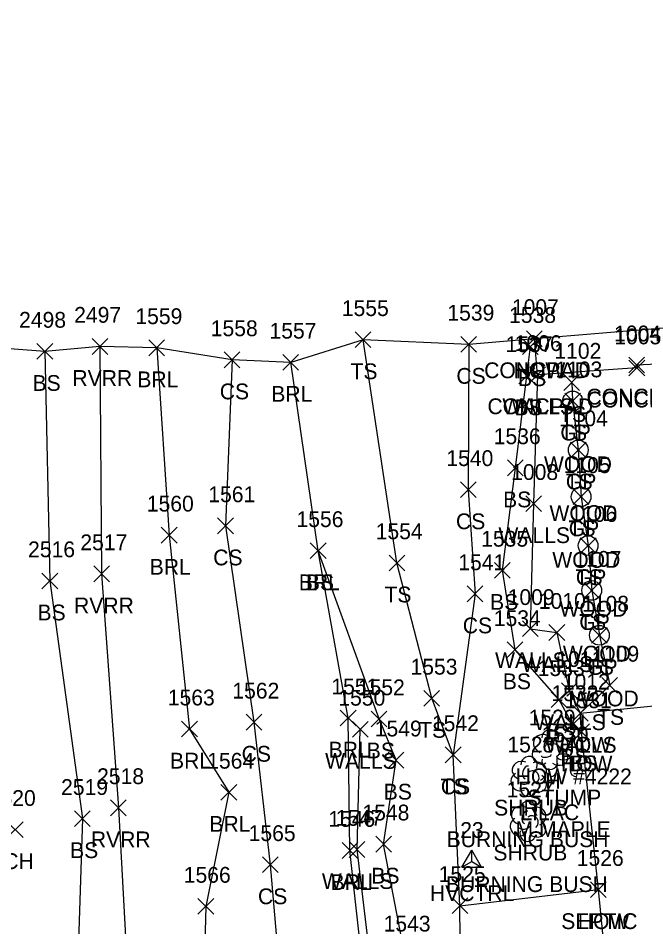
# Model space of a CAD drawing. Extents: x 1512665 to 1513714, y 110636 to 112816.
# Drawn here: x 1513047.2 to 1513126.6, y 111019.1 to 111134.2 of the extents above; entities that cross this region are included whole.
import ezdxf

# ---------------------------------------------------------------- set-up
doc = ezdxf.new("R2010")
doc.units = 0
for name, color, linetype in [('C_A', 7, 'Continuous'), ('C_I', 7, 'Continuous'), ('CPSM', 7, 'Continuous'), ('L_A', 7, 'Continuous'), ('L_C', 7, 'Continuous'), ('L_I', 7, 'Continuous'), ('L_TIC', 7, 'Continuous'), ('LABL', 7, 'Continuous'), ('LAWE', 7, 'Continuous'), ('LBC', 7, 'Continuous'), ('LELB', 7, 'Continuous'), ('Level 13', 7, 'Continuous'), ('LS', 7, 'Continuous'), ('LSH', 7, 'Continuous'), ('LSOGP', 7, 'Continuous'), ('LTD', 7, 'Continuous'), ('LTS', 7, 'Continuous'), ('LWS', 7, 'Continuous'), ('R_A', 7, 'Continuous'), ('R_C', 7, 'Continuous'), ('R_I', 7, 'Continuous'), ('RGP', 7, 'Continuous'), ('U_A', 7, 'Continuous'), ('U_I', 7, 'Continuous'), ('U_TIC', 7, 'Continuous'), ('USA', 7, 'Continuous')]:
    doc.layers.add(name, color=color, linetype=linetype)

msp = doc.modelspace()

# ---------------------------------------------------------------- linework, layer by layer
at = {"layer": 'CPSM'}
for p, q in [((1513103.4, 111026.62), (1513104.65, 111028.78)), ((1513105.9, 111026.62), (1513104.65, 111028.78)), ((1513104.65, 111027.34), (1513104.65, 111028.78)), ((1513103.4, 111026.62), (1513104.65, 111027.34)), ((1513104.65, 111027.34), (1513104.65, 111027.34)), ((1513104.65, 111027.34), (1513105.9, 111026.62)), ((1513103.4, 111026.62), (1513105.9, 111026.62))]:
    msp.add_line(p, q, dxfattribs=at)
at = {"layer": 'L_TIC'}
for points in [[(1513056.55, 111091.59), (1513058.55, 111093.59)], [(1513058.55, 111091.59), (1513056.55, 111093.59)], [(1513089.88, 111092.44), (1513091.88, 111094.44)], [(1513091.88, 111092.44), (1513089.88, 111094.44)], [(1513103.26, 111091.86), (1513105.26, 111093.86)], [(1513105.26, 111091.86), (1513103.26, 111093.86)], [(1513111.07, 111091.57), (1513113.07, 111093.57)], [(1513113.07, 111091.57), (1513111.07, 111093.57)], [(1513111.58, 111092.57), (1513113.58, 111094.57)], [(1513113.58, 111092.57), (1513111.58, 111094.57)], [(1513111.58, 111092.57), (1513113.58, 111094.57)], [(1513113.58, 111092.57), (1513111.58, 111094.57)], [(1513049.57, 111090.96), (1513051.57, 111092.96)], [(1513051.57, 111090.96), (1513049.57, 111092.96)], [(1513063.74, 111091.42), (1513065.74, 111093.42)], [(1513065.74, 111091.42), (1513063.74, 111093.42)], [(1513073.29, 111089.89), (1513075.29, 111091.89)], [(1513075.29, 111089.89), (1513073.29, 111091.89)], [(1513080.72, 111089.58), (1513082.72, 111091.58)], [(1513082.72, 111089.58), (1513080.72, 111091.58)], [(1513124.53, 111089.23), (1513126.53, 111091.23)], [(1513126.53, 111089.23), (1513124.53, 111091.23)], [(1513124.56, 111088.86), (1513126.56, 111090.86)], [(1513126.56, 111088.86), (1513124.56, 111090.86)], [(1513110.62, 111087.87), (1513112.62, 111089.87)], [(1513112.62, 111087.87), (1513110.62, 111089.87)], [(1513111.99, 111088.01), (1513113.99, 111090.01)], [(1513113.99, 111088.01), (1513111.99, 111090.01)], [(1513111.99, 111088.01), (1513113.99, 111090.01)], [(1513113.99, 111088.01), (1513111.99, 111090.01)], [(1513116.31, 111087.03), (1513118.31, 111089.03)], [(1513118.31, 111087.03), (1513116.31, 111089.03)], [(1513116.43, 111084.68), (1513118.43, 111086.68)], [(1513118.43, 111084.68), (1513116.43, 111086.68)], [(1513117.14, 111078.48), (1513119.14, 111080.48)], [(1513119.14, 111078.48), (1513117.14, 111080.48)], [(1513109.18, 111076.21), (1513111.18, 111078.21)], [(1513111.18, 111076.21), (1513109.18, 111078.21)], [(1513103.21, 111073.44), (1513105.21, 111075.44)], [(1513105.21, 111073.44), (1513103.21, 111075.44)], [(1513117.5, 111072.55), (1513119.5, 111074.55)], [(1513119.5, 111072.55), (1513117.5, 111074.55)], [(1513111.49, 111071.68), (1513113.49, 111073.68)], [(1513113.49, 111071.68), (1513111.49, 111073.68)], [(1513072.46, 111068.86), (1513074.46, 111070.86)], [(1513074.46, 111068.86), (1513072.46, 111070.86)], [(1513065.32, 111067.68), (1513067.32, 111069.68)], [(1513067.32, 111067.68), (1513065.32, 111069.68)], [(1513118.39, 111066.36), (1513120.39, 111068.36)], [(1513120.39, 111066.36), (1513118.39, 111068.36)], [(1513084.19, 111065.71), (1513086.19, 111067.71)], [(1513086.19, 111065.71), (1513084.19, 111067.71)], [(1513084.19, 111065.71), (1513086.19, 111067.71)], [(1513086.19, 111065.71), (1513084.19, 111067.71)], [(1513094.18, 111064.17), (1513096.18, 111066.17)], [(1513096.18, 111064.17), (1513094.18, 111066.17)], [(1513107.53, 111063.23), (1513109.53, 111065.23)], [(1513109.53, 111063.23), (1513107.53, 111065.23)], [(1513050.2, 111061.89), (1513052.2, 111063.89)], [(1513052.2, 111061.89), (1513050.2, 111063.89)], [(1513056.76, 111062.78), (1513058.76, 111064.78)], [(1513058.76, 111062.78), (1513056.76, 111064.78)], [(1513118.84, 111060.68), (1513120.84, 111062.68)], [(1513120.84, 111060.68), (1513118.84, 111062.68)], [(1513104.07, 111060.25), (1513106.07, 111062.25)], [(1513106.07, 111060.25), (1513104.07, 111062.25)], [(1513111.06, 111055.84), (1513113.06, 111057.84)], [(1513113.06, 111055.84), (1513111.06, 111057.84)], [(1513114.43, 111055.35), (1513116.43, 111057.35)], [(1513116.43, 111055.35), (1513114.43, 111057.35)], [(1513119.82, 111055), (1513121.82, 111057)], [(1513121.82, 111055), (1513119.82, 111057)], [(1513109.14, 111053.17), (1513111.14, 111055.17)], [(1513111.14, 111053.17), (1513109.14, 111055.17)], [(1513116, 111047.99), (1513118, 111049.99)], [(1513118, 111047.99), (1513116, 111049.99)], [(1513121.12, 111048.66), (1513123.12, 111050.66)], [(1513123.12, 111048.66), (1513121.12, 111050.66)], [(1513098.58, 111047.02), (1513100.58, 111049.02)], [(1513100.58, 111047.02), (1513098.58, 111049.02)], [(1513114.71, 111046.84), (1513116.71, 111048.84)], [(1513116.71, 111046.84), (1513114.71, 111048.84)], [(1513087.99, 111044.52), (1513089.99, 111046.52)], [(1513089.99, 111044.52), (1513087.99, 111046.52)], [(1513091.91, 111044.41), (1513093.91, 111046.41)], [(1513093.91, 111044.41), (1513091.91, 111046.41)], [(1513117.39, 111045.13), (1513119.39, 111047.13)], [(1513119.39, 111045.13), (1513117.39, 111047.13)], [(1513117.39, 111045.13), (1513119.39, 111047.13)], [(1513119.39, 111045.13), (1513117.39, 111047.13)], [(1513117.39, 111045.13), (1513119.39, 111047.13)], [(1513119.39, 111045.13), (1513117.39, 111047.13)], [(1513076.06, 111043.99), (1513078.06, 111045.99)], [(1513078.06, 111043.99), (1513076.06, 111045.99)], [(1513116.44, 111043.66), (1513118.44, 111045.66)], [(1513118.44, 111043.66), (1513116.44, 111045.66)], [(1513067.89, 111043.12), (1513069.89, 111045.12)], [(1513069.89, 111043.12), (1513067.89, 111045.12)], [(1513089.53, 111043.09), (1513091.53, 111045.09)], [(1513091.53, 111043.09), (1513089.53, 111045.09)], [(1513117.56, 111042.77), (1513119.56, 111044.77)], [(1513119.56, 111042.77), (1513117.56, 111044.77)], [(1513117.56, 111042.77), (1513119.56, 111044.77)], [(1513119.56, 111042.77), (1513117.56, 111044.77)], [(1513117.56, 111042.77), (1513119.56, 111044.77)], [(1513119.56, 111042.77), (1513117.56, 111044.77)], [(1513101.29, 111039.86), (1513103.29, 111041.86)], [(1513103.29, 111039.86), (1513101.29, 111041.86)], [(1513101.29, 111039.86), (1513103.29, 111041.86)], [(1513103.29, 111039.86), (1513101.29, 111041.86)], [(1513094.06, 111039.19), (1513096.06, 111041.19)], [(1513096.06, 111039.19), (1513094.06, 111041.19)], [(1513072.88, 111035.11), (1513074.88, 111037.11)], [(1513074.88, 111035.11), (1513072.88, 111037.11)], [(1513058.89, 111033.15), (1513060.89, 111035.15)], [(1513060.89, 111033.15), (1513058.89, 111035.15)], [(1513054.33, 111031.78), (1513056.33, 111033.78)], [(1513056.33, 111031.78), (1513054.33, 111033.78)], [(1513045.82, 111030.39), (1513047.82, 111032.39)], [(1513047.82, 111030.39), (1513045.82, 111032.39)], [(1513092.49, 111028.55), (1513094.49, 111030.55)], [(1513094.49, 111028.55), (1513092.49, 111030.55)], [(1513088.22, 111027.74), (1513090.22, 111029.74)], [(1513090.22, 111027.74), (1513088.22, 111029.74)], [(1513089.12, 111027.87), (1513091.12, 111029.87)], [(1513091.12, 111027.87), (1513089.12, 111029.87)], [(1513078.13, 111025.94), (1513080.13, 111027.94)], [(1513080.13, 111025.94), (1513078.13, 111027.94)], [(1513119.69, 111022.79), (1513121.69, 111024.79)], [(1513121.69, 111022.79), (1513119.69, 111024.79)], [(1513069.96, 111020.66), (1513071.96, 111022.66)], [(1513071.96, 111020.66), (1513069.96, 111022.66)], [(1513102.15, 111020.75), (1513104.15, 111022.75)], [(1513104.15, 111020.75), (1513102.15, 111022.75)]]:
    msp.add_lwpolyline(points, dxfattribs=at)
at = {"layer": 'LABL'}
for points in [[(1513064.74, 111092.42), (1513066.32, 111068.68), (1513068.89, 111044.12), (1513073.88, 111036.11), (1513070.96, 111021.66), (1513070.42, 111001.37), (1513070.1, 110988.57), (1513073.06, 110969.79), (1513079.94, 110970.83), (1513085.92, 110971.63)], [(1513094.41, 110975.3), (1513092.4, 110994.9), (1513090.91, 111013.45), (1513089.22, 111028.74), (1513088.99, 111045.52), (1513085.19, 111066.71), (1513081.72, 111090.58)]]:
    msp.add_lwpolyline(points, dxfattribs=at)
at = {"layer": 'LAWE'}
msp.add_lwpolyline([(1513057.55, 111092.59), (1513057.76, 111063.78), (1513059.89, 111034.15), (1513061.78, 110999.93), (1513066.11, 110974.8), (1513067.08, 110953.86)], dxfattribs=at)
at = {"layer": 'LBC'}
for points in [[(1513134.02, 111127.97), (1513137.06, 111095.56), (1513112.58, 111093.57)], [(1513118.39, 111046.13), (1513128.97, 111047.21), (1513141.84, 111048.52), (1513143.29, 111036.99), (1513150.61, 111037.66), (1513151.29, 111036.53), (1513151.86, 111031.98), (1513152.24, 111029.89), (1513144.2, 111028.94), (1513145.36, 111017.71), (1513137.39, 111016.83), (1513138.65, 111001.1), (1513139.17, 110995.77), (1513139.38, 110992.13), (1513138.77, 110991.85), (1513123.65, 110990.59), (1513123.34, 110990.75), (1513123.27, 110992.81), (1513122.61, 111004.46), (1513120.69, 111023.79), (1513118.56, 111043.77)], [(1513118.39, 111046.13), (1513118.56, 111043.77)]]:
    msp.add_lwpolyline(points, dxfattribs=at)
at = {"layer": 'LELB'}
for points in [[(1513103.15, 111021.75), (1513102.29, 111040.86), (1513099.58, 111048.02), (1513095.18, 111065.17), (1513090.88, 111093.44)], [(1513104.26, 111092.86), (1513104.21, 111074.44), (1513105.07, 111061.25), (1513102.29, 111040.86)], [(1513118.56, 111043.77), (1513117.44, 111044.66), (1513115.71, 111047.84), (1513110.14, 111054.17), (1513108.53, 111064.23), (1513110.18, 111077.21), (1513111.62, 111088.87), (1513112.07, 111092.57)], [(1513050.57, 111091.96), (1513051.2, 111062.89), (1513055.33, 111032.78), (1513054.28, 111000.38), (1513059.51, 110973.72), (1513056.82, 110953.44), (1513063.6, 110941.61), (1513067.13, 110927.73), (1513070.91, 110916.69), (1513076.1, 110900.54), (1513074.96, 110895.68), (1513079.69, 110884.14), (1513081.25, 110868.38), (1513078.34, 110857.81), (1513080.52, 110848.08), (1513078.46, 110838.38), (1513078.11, 110823.81), (1513078.51, 110819.27), (1513078.06, 110816.05), (1513076.99, 110814.7), (1513073.49, 110811.48), (1513073.8, 110795.94), (1513074.51, 110793.14), (1513077.43, 110790.98)], [(1513074.29, 111090.89), (1513073.46, 111069.86), (1513077.06, 111044.99), (1513079.13, 111026.94), (1513081.17, 111003.04), (1513084.44, 110991.21), (1513085.92, 110971.63), (1513087.54, 110964.28), (1513094.93, 110950.26), (1513100.49, 110942.42), (1513104.75, 110930.66), (1513102.64, 110919.33), (1513100.96, 110909.74), (1513100.96, 110887.48)], [(1513117.31, 111088.03), (1513117.43, 111085.68), (1513118.14, 111079.48), (1513118.5, 111073.55), (1513119.39, 111067.36), (1513119.84, 111061.68), (1513120.82, 111056), (1513122.12, 111049.66)], [(1513105.19, 110981.77), (1513102.58, 110989.9), (1513098.9, 111009.19), (1513096.17, 111015.48), (1513093.49, 111029.55), (1513095.06, 111040.19), (1513092.91, 111045.41), (1513085.19, 111066.71)], [(1513122.12, 111049.66), (1513118.39, 111046.13)]]:
    msp.add_lwpolyline(points, dxfattribs=at)
at = {"layer": 'Level 13'}
msp.add_lwpolyline([(1513123.64, 110990.61), (1513123.35, 110990.76), (1513123.29, 110992.81), (1513122.62, 111004.46), (1513120.7, 111023.79), (1513118.57, 111043.77), (1513118.4, 111046.12), (1513128.98, 111047.2), (1513141.84, 111048.51), (1513143.27, 111036.98), (1513150.61, 111037.65), (1513151.28, 111036.53), (1513151.85, 111031.98), (1513152.22, 111029.9), (1513144.19, 111028.96), (1513145.35, 111017.72), (1513137.37, 111016.84), (1513138.63, 111001.1), (1513139.16, 110995.77), (1513139.37, 110992.14), (1513138.78, 110991.85)], close=True, dxfattribs=at)
at = {"layer": 'LS'}
msp.add_lwpolyline([(1513137.06, 111095.56), (1513137.54, 111090.82), (1513125.53, 111090.23), (1513125.56, 111089.86), (1513112.99, 111089.01), (1513112.58, 111093.57)], dxfattribs=at)
at = {"layer": 'LSH'}
for p, q in [((1513111.85, 111038.17), (1513111.85, 111038.17)), ((1513111.85, 111038.17), (1513111.85, 111038.17)), ((1513111.76, 111032.48), (1513111.76, 111032.48)), ((1513111.76, 111032.48), (1513111.76, 111032.48))]:
    msp.add_line(p, q, dxfattribs=at)
for centre in [(1513111.9, 111039.6), (1513111.81, 111033.92)]:
    msp.add_arc(centre, 1.05, 335.5272, 180.9563, dxfattribs=at)
for centre, major_axis, ratio, start_param, end_param in [((1513111.06, 111038.84), (1.21, -0.51), 0.895232, 1.570796, 4.712389), ((1513111.64, 111038.63), (-0.208, -0.792), 0.645439, 3.141593, 6.283185), ((1513112.89, 111038.75), (-1.14, -0.48), 0.949671, 1.570796, 4.712389), ((1513110.77, 111037.46), (0.58, -1.04), 0.959034, 3.141593, 6.283185), ((1513112.35, 111038), (-0.5, 0.667), 0.989748, 3.141593, 6.283185), ((1513111.39, 111037.42), (-0.625, -0.083), 0.423636, 0, 3.141593), ((1513112.85, 111037.34), (-1.09, 0.79), 0.841452, 1.570796, 4.712389), ((1513111.85, 111036.67), (0.26, 1.06), 0.942809, 1.570796, 4.712389), ((1513110.97, 111033.15), (1.21, -0.51), 0.895232, 1.570796, 4.712389), ((1513111.55, 111032.94), (-0.208, -0.792), 0.645439, 3.141593, 6.283185), ((1513112.8, 111033.06), (-1.14, -0.48), 0.949671, 1.570796, 4.712389), ((1513110.68, 111031.77), (0.58, -1.04), 0.959034, 3.141593, 6.283185), ((1513112.26, 111032.31), (-0.5, 0.667), 0.989748, 3.141593, 6.283185), ((1513112.76, 111031.65), (-1.09, 0.79), 0.841452, 1.570796, 4.712389), ((1513111.3, 111031.73), (-0.625, -0.083), 0.423636, 0, 3.141593), ((1513111.76, 111030.98), (0.26, 1.06), 0.942809, 1.570796, 4.712389)]:
    msp.add_ellipse(centre, major_axis=major_axis, ratio=ratio, start_param=start_param, end_param=end_param, dxfattribs=at)
at = {"layer": 'LSOGP'}
msp.add_lwpolyline([(1513210.3, 111134.17), (1513195.74, 111132.86), (1513181.78, 111131.32), (1513177.7, 111131.29), (1513170.22, 111130.81), (1513157.92, 111130.1), (1513134.02, 111127.97), (1513137.06, 111095.56), (1513112.58, 111093.57), (1513104.26, 111092.85), (1513090.88, 111093.44), (1513081.72, 111090.57), (1513074.29, 111090.88), (1513064.74, 111092.42), (1513057.55, 111092.59), (1513050.57, 111091.96), (1513042.76, 111092.55)], dxfattribs=at)
at = {"layer": 'LTD'}
msp.add_line((1513114.55, 111041.58), (1513114.55, 111041.58), dxfattribs=at)
msp.add_line((1513114.55, 111041.58), (1513114.55, 111041.58), dxfattribs=at)
msp.add_arc((1513114.59, 111043.01), 1.05, 335.5272, 180.9563, dxfattribs=at)
for centre, major_axis, ratio, start_param, end_param in [((1513113.75, 111042.24), (1.21, -0.51), 0.895232, 1.570796, 4.712389), ((1513115.59, 111042.16), (-1.14, -0.48), 0.949671, 1.570796, 4.712389), ((1513113.46, 111040.87), (0.58, -1.04), 0.959034, 3.141593, 6.283185), ((1513114.34, 111042.04), (-0.208, -0.792), 0.645439, 3.141593, 6.283185), ((1513115.05, 111041.41), (-0.5, 0.667), 0.989748, 3.141593, 6.283185), ((1513114.09, 111040.83), (-0.625, -0.083), 0.423636, 0, 3.141593), ((1513115.55, 111040.74), (-1.09, 0.79), 0.841452, 1.570796, 4.712389), ((1513114.55, 111040.08), (0.26, 1.06), 0.942809, 1.570796, 4.712389)]:
    msp.add_ellipse(centre, major_axis=major_axis, ratio=ratio, start_param=start_param, end_param=end_param, dxfattribs=at)
at = {"layer": 'LTS'}
for p, q in [((1513115.43, 111040.59), (1513115.43, 111038.93)), ((1513117.1, 111040.43), (1513117.1, 111040.59)), ((1513117.1, 111040.59), (1513117.1, 111038.93)), ((1513116.27, 111039.45), (1513116.27, 111039.45)), ((1513116.27, 111039.45), (1513116.27, 111039.45)), ((1513116.27, 111039.43), (1513116.27, 111039.43))]:
    msp.add_line(p, q, dxfattribs=at)
msp.add_circle((1513116.27, 111039.45), 0.0833, dxfattribs=at)
for centre, start, end in [((1513114.6, 111038.93), 270, 360), ((1513117.93, 111038.93), 180, 270)]:
    msp.add_arc(centre, 0.833, start, end, dxfattribs=at)
msp.add_ellipse((1513116.27, 111040.59), major_axis=(-0.833, 0), ratio=0.5, dxfattribs=at)
at = {"layer": 'LWS'}
for points in [[(1513112.99, 111089.01), (1513112.49, 111072.68), (1513112.06, 111056.84), (1513115.43, 111056.35), (1513117, 111048.99), (1513118.39, 111046.13)], [(1513113.24, 110946.25), (1513110.87, 110954.65), (1513106.11, 110963.52), (1513095.31, 110975.46), (1513093.16, 110995.74), (1513091.91, 111014.04), (1513090.12, 111028.87), (1513090.53, 111044.09)]]:
    msp.add_lwpolyline(points, dxfattribs=at)
at = {"layer": 'RGP'}
for p, q in [((1513117.43, 111085.68), (1513117.43, 111085.68)), ((1513118.14, 111079.48), (1513118.14, 111079.48)), ((1513118.5, 111073.55), (1513118.5, 111073.55)), ((1513119.39, 111067.36), (1513119.39, 111067.36)), ((1513119.84, 111061.68), (1513119.84, 111061.68)), ((1513120.82, 111056), (1513120.82, 111056))]:
    msp.add_line(p, q, dxfattribs=at)
for centre, radius in [((1513117.43, 111085.68), 1.25), ((1513117.43, 111085.68), 0.0833), ((1513118.14, 111079.48), 1.25), ((1513118.14, 111079.48), 0.0833), ((1513118.5, 111073.55), 1.25), ((1513118.5, 111073.55), 0.0833), ((1513119.39, 111067.36), 1.25), ((1513119.39, 111067.36), 0.0833), ((1513119.84, 111061.68), 1.25), ((1513119.84, 111061.68), 0.0833), ((1513120.82, 111056), 1.25), ((1513120.82, 111056), 0.0833)]:
    msp.add_circle(centre, radius, dxfattribs=at)
at = {"layer": 'U_TIC'}
for points in [[(1513119.69, 111022.79), (1513121.69, 111024.79)], [(1513121.69, 111022.79), (1513119.69, 111024.79)], [(1513102.15, 111020.75), (1513104.15, 111022.75)], [(1513104.15, 111020.75), (1513102.15, 111022.75)]]:
    msp.add_lwpolyline(points, dxfattribs=at)
at = {"layer": 'USA'}
msp.add_lwpolyline([(1513119.97, 110992.38), (1513106.59, 110990.46), (1513103.28, 111009.25), (1513103.15, 111021.75), (1513120.69, 111023.79)], dxfattribs=at)

# ---------------------------------------------------------------- texts
at = {"layer": 'C_A'}
msp.add_text('HVCTRL', height=2, dxfattribs=at).set_placement((1513099.35, 111022.34))
at = {"layer": 'C_I'}
msp.add_text('23', height=2, dxfattribs=at).set_placement((1513103.19, 111030.34))
at = {"layer": 'L_A'}
for s, p in [('TS', (1513089.29, 111088.44)), ('CONCPAD', (1513106.22, 111088.57)), ('HOW', (1513109.96, 111088.57)), ('BS', (1513049.01, 111086.96)), ('RVRR', (1513054.06, 111087.59)), ('BRL', (1513062.29, 111087.42)), ('CS', (1513102.7, 111087.86)), ('BS', (1513110.51, 111087.57)), ('CS', (1513072.73, 111085.89)), ('BRL', (1513079.26, 111085.58)), ('CONCPAD', (1513119.18, 111085.23)), ('CONCPAD', (1513119.21, 111084.86)), ('CONCPAD', (1513106.64, 111084.01)), ('WALLS', (1513108.53, 111084.01)), ('BS', (1513110.06, 111083.87)), ('TS', (1513115.72, 111083.03)), ('TS', (1513115.84, 111080.68)), ('TS', (1513116.55, 111074.48)), ('BS', (1513108.62, 111072.21)), ('CS', (1513102.65, 111069.44)), ('TS', (1513116.91, 111068.55)), ('WALLS', (1513108.03, 111067.68)), ('CS', (1513071.9, 111064.86)), ('BRL', (1513063.86, 111063.68)), ('BRL', (1513082.74, 111061.71)), ('BS', (1513083.64, 111061.71)), ('TS', (1513117.8, 111062.36)), ('TS', (1513093.59, 111060.17)), ('RVRR', (1513054.27, 111058.78)), ('BS', (1513106.97, 111059.23)), ('BS', (1513049.64, 111057.89)), ('CS', (1513103.51, 111056.25)), ('TS', (1513118.25, 111056.68)), ('WALLS', (1513107.6, 111051.84)), ('WALLS', (1513110.97, 111051.35)), ('TS', (1513119.23, 111051)), ('BS', (1513108.58, 111049.17)), ('TS', (1513120.53, 111044.66)), ('WALLS', (1513112.55, 111043.99)), ('TS', (1513097.99, 111043.02)), ('BS', (1513114.15, 111042.84)), ('WALLS', (1513113.93, 111041.13)), ('HOW', (1513115.77, 111041.13)), ('HOW', (1513115.77, 111041.13)), ('CS', (1513075.5, 111039.99)), ('BRL', (1513086.53, 111040.52)), ('BS', (1513091.35, 111040.41)), ('BRL', (1513066.43, 111039.12)), ('WALLS', (1513086.07, 111039.09)), ('BS', (1513115.88, 111039.66)), ('HOW', (1513115.94, 111038.77)), ('HOW', (1513115.94, 111038.77)), ('BS', (1513117, 111038.77)), ('H', (1513113.98, 111036.58)), ('BS', (1513093.5, 111035.19)), ('TS', (1513100.7, 111035.86)), ('CS', (1513100.73, 111035.86)), ('STUMP', (1513111.69, 111034.45)), ('SHRUB', (1513107.48, 111033.17)), ('BRL', (1513071.42, 111031.11)), ('RVRR', (1513056.4, 111029.15)), ('BS', (1513053.77, 111027.78)), ('SHRUB', (1513107.39, 111027.48)), ('CH', (1513045.31, 111026.39)), ('WALLS', (1513085.66, 111023.87)), ('BRL', (1513086.77, 111023.74)), ('BS', (1513091.93, 111024.55)), ('CS', (1513077.57, 111021.94)), ('HOW', (1513118.08, 111018.79))]:
    msp.add_text(s, height=2, dxfattribs=at).set_placement(p)
at = {"layer": 'L_C'}
for s, p in [('HOW #4222', (1513110.21, 111037.13)), ('HOW #4222', (1513110.21, 111037.13)), ('LILAC', (1513110.82, 111032.58)), ('M.MAPLE', (1513110.2, 111030.45)), ('BURNING BUSH', (1513101.47, 111029.17)), ('BURNING BUSH', (1513101.38, 111023.48))]:
    msp.add_text(s, height=2, dxfattribs=at).set_placement(p)
at = {"layer": 'L_I'}
for s, p in [('1555', (1513088.19, 111096.44)), ('1007', (1513109.73, 111096.57)), ('1007', (1513109.73, 111096.57)), ('2497', (1513054.29, 111095.59)), ('1559', (1513062.04, 111095.42)), ('1539', (1513101.56, 111095.86)), ('1538', (1513109.38, 111095.57)), ('2498', (1513047.31, 111094.96)), ('1558', (1513071.59, 111093.89)), ('1557', (1513079.03, 111093.58)), ('1004', (1513122.68, 111093.23)), ('1005', (1513122.71, 111092.86)), ('1537', (1513108.93, 111091.87)), ('1006', (1513110.09, 111092.01)), ('1006', (1513110.09, 111092.01)), ('1102', (1513115.11, 111091.03)), ('1103', (1513115.23, 111088.68)), ('1104', (1513115.93, 111082.48)), ('1536', (1513107.43, 111080.21)), ('1540', (1513101.43, 111077.44)), ('1008', (1513109.64, 111075.68)), ('1105', (1513116.29, 111076.55)), ('1561', (1513071.28, 111072.86)), ('1560', (1513063.49, 111071.68)), ('1556', (1513082.45, 111069.71)), ('1556', (1513082.45, 111069.71)), ('1106', (1513117.13, 111070.36)), ('1554', (1513092.48, 111068.17)), ('2517', (1513055.07, 111066.78)), ('1535', (1513105.84, 111067.23)), ('2516', (1513048.45, 111065.89)), ('1541', (1513102.94, 111064.25)), ('1107', (1513117.64, 111064.68)), ('1009', (1513109.2, 111059.84)), ('1010', (1513113.14, 111059.35)), ('1108', (1513118.62, 111059)), ('1534', (1513107.44, 111057.17)), ('1109', (1513119.91, 111052.66)), ('1011', (1513115.36, 111051.99)), ('1553', (1513096.89, 111051.02)), ('1533', (1513113.01, 111050.84)), ('1012', (1513116.18, 111049.13)), ('1012', (1513116.18, 111049.13)), ('1012', (1513116.18, 111049.13)), ('1562', (1513074.32, 111047.99)), ('1551', (1513086.86, 111048.52)), ('1552', (1513090.22, 111048.41)), ('1563', (1513066.15, 111047.12)), ('1550', (1513087.75, 111047.09)), ('1532', (1513114.75, 111047.66)), ('1531', (1513116.43, 111046.77)), ('1531', (1513116.43, 111046.77)), ('1531', (1513116.43, 111046.77)), ('1529', (1513111.85, 111044.58)), ('1542', (1513099.6, 111043.86)), ('1542', (1513099.6, 111043.86)), ('1549', (1513092.36, 111043.19)), ('1530', (1513113.48, 111042.45)), ('1528', (1513109.16, 111041.17)), ('1564', (1513071.14, 111039.11)), ('2518', (1513057.19, 111037.15)), ('2519', (1513052.63, 111035.78)), ('1527', (1513109.07, 111035.48)), ('2520', (1513043.47, 111034.39)), ('1546', (1513086.47, 111031.74)), ('1547', (1513087.42, 111031.87)), ('1548', (1513090.8, 111032.55)), ('1565', (1513076.39, 111029.94)), ('1526', (1513117.95, 111026.79)), ('1566', (1513068.17, 111024.66)), ('1525', (1513100.46, 111024.75)), ('1543', (1513093.48, 111018.48))]:
    msp.add_text(s, height=2, dxfattribs=at).set_placement(p)
at = {"layer": 'R_A'}
for p in [(1513115.87, 111080.68), (1513116.57, 111074.48), (1513116.93, 111068.55), (1513117.83, 111062.36), (1513118.27, 111056.68), (1513119.26, 111051)]:
    msp.add_text('GP', height=2, dxfattribs=at).set_placement(p)
at = {"layer": 'R_C'}
for p in [(1513113.79, 111076.68), (1513114.49, 111070.48), (1513114.85, 111064.55), (1513115.75, 111058.36), (1513116.19, 111052.68), (1513117.18, 111047)]:
    msp.add_text('WOOD', height=2, dxfattribs=at).set_placement(p)
at = {"layer": 'R_I'}
for s, p in [('1103', (1513115.23, 111088.68)), ('1104', (1513115.93, 111082.48)), ('1105', (1513116.29, 111076.55)), ('1106', (1513117.13, 111070.36)), ('1107', (1513117.64, 111064.68)), ('1108', (1513118.62, 111059))]:
    msp.add_text(s, height=2, dxfattribs=at).set_placement(p)
at = {"layer": 'U_A'}
msp.add_text('SEPTIC', height=2, dxfattribs=at).set_placement((1513115.98, 111018.79))
at = {"layer": 'U_I'}
for s, p in [('1526', (1513117.95, 111026.79)), ('1525', (1513100.46, 111024.75))]:
    msp.add_text(s, height=2, dxfattribs=at).set_placement(p)

doc.saveas('drawing.dxf')
